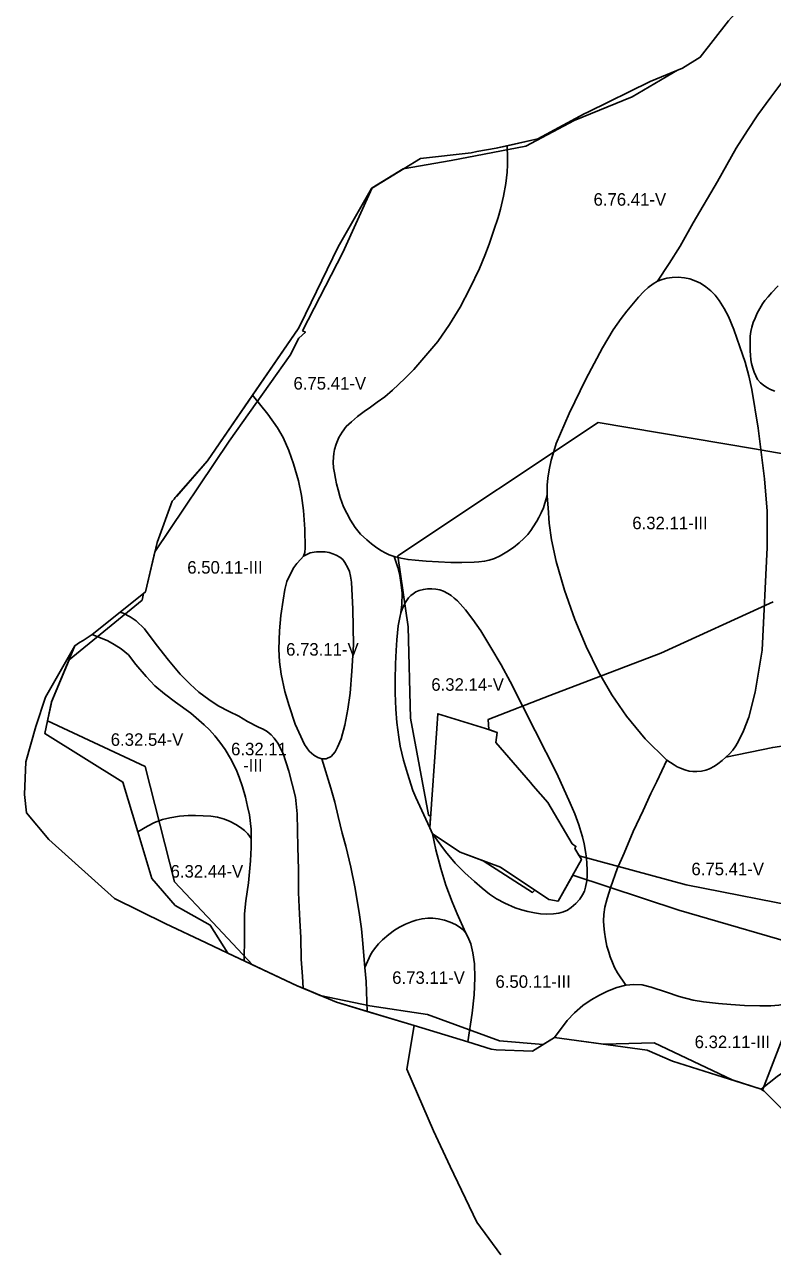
# Model space of a CAD drawing. Extents: x -555156 to -540209, y -1046851 to -1035695.
# Drawn here: x -545232 to -544635, y -1042568 to -1041591 of the extents above; entities that cross this region are included whole.
import ezdxf

# ---------------------------------------------------------------- set-up
doc = ezdxf.new("R2010")
doc.units = 0
for name, color, linetype in [('Vrstva 27', 7, 'Continuous'), ('Vrstva 28', 7, 'Continuous'), ('Vrstva 29', 7, 'Continuous')]:
    doc.layers.add(name, color=color, linetype=linetype)

msp = doc.modelspace()

# ---------------------------------------------------------------- linework, layer by layer
at = {"layer": 'Vrstva 28'}
for points in [[(-544846.66, -1041687.71), (-544822.15, -1041682.29), (-544785.01, -1041662.41), (-544782.28, -1041660.95), (-544732.45, -1041636.53), (-544706.67, -1041625.81), (-544692.4, -1041617.08), (-544669.81, -1041587.89), (-544667.51, -1041585.3), (-544652.1, -1041568.04), (-544642.56, -1041556.41), (-544641.15, -1041554.7), (-544627.44, -1041537.8), (-544618.31, -1041526.55), (-544597.99, -1041504.33), (-544579.99, -1041481.73), (-544578.85, -1041475.94), (-544576.99, -1041466.5), (-544570.58, -1041421.76), (-544570.32, -1041418.62), (-544569.32, -1041406.66), (-544568.61, -1041387.02), (-544567.8, -1041372.55)], [(-544669.81, -1041587.89), (-544692.4, -1041617.08), (-544706.67, -1041625.81), (-544732.45, -1041636.53), (-544782.28, -1041660.95), (-544785.01, -1041662.41), (-544811.22, -1041676.44), (-544822.15, -1041682.29), (-544855.46, -1041689.66), (-544870.74, -1041692.46), (-544875.3, -1041693.3), (-544915.78, -1041697.83), (-544954.95, -1041721.8), (-544981.68, -1041768.53), (-545011.97, -1041830.94), (-545013.49, -1041834.07), (-545085.98, -1041939.48), (-545110.52, -1041967.55), (-545110.82, -1041967.9), (-545111.62, -1041968.81), (-545112.68, -1041970.02), (-545114.1, -1041971.65), (-545126.15, -1042004.64), (-545135.45, -1042044.15), (-545177.97, -1042078.09), (-545185.22, -1042082.8), (-545188.03, -1042084.62), (-545191.76, -1042087.04), (-545215.32, -1042128.08), (-545222.89, -1042151.63), (-545231, -1042179.76), (-545232.1, -1042206), (-545230.38, -1042220.45), (-545212.6, -1042241.9), (-545160.15, -1042288.85), (-545119.62, -1042309.04), (-545087.05, -1042324.33), (-545069.69, -1042332.51), (-545014.29, -1042358.62), (-544982.93, -1042371.86), (-544920.79, -1042390.48), (-544926.73, -1042425.19), (-544905.36, -1042474.42), (-544892.12, -1042503.11), (-544870.74, -1042547.47), (-544851.56, -1042573.64)], [(-544626.51, -1041636.32), (-544636.08, -1041648.92), (-544646.38, -1041663.1), (-544654.61, -1041675.46), (-544663.75, -1041689.7), (-544678.59, -1041716.21), (-544698.08, -1041749.29), (-544708.47, -1041767.95), (-544717.16, -1041781.73), (-544726.5, -1041795.92)], [(-545049.88, -1041886.99), (-545013.49, -1041834.07), (-545011.97, -1041830.94), (-544981.68, -1041768.53), (-544954.95, -1041721.8), (-544915.78, -1041697.83), (-544875.3, -1041693.3), (-544870.74, -1041692.46), (-544855.46, -1041689.66), (-544846.66, -1041687.71)], [(-544846.66, -1041687.71), (-544846.27, -1041697.25)], [(-544846.27, -1041697.25), (-544846.27, -1041703.07), (-544846.63, -1041709), (-544847.6, -1041717.97), (-544849.66, -1041728.03), (-544851.96, -1041738.45), (-544853.9, -1041745.11), (-544857.17, -1041755.29), (-544861.04, -1041766.44), (-544864.55, -1041775.41), (-544868.62, -1041785.86), (-544876.46, -1041801.76), (-544884.09, -1041816.6), (-544892.78, -1041830.6), (-544902.11, -1041844.17), (-544911.64, -1041855.41), (-544921.18, -1041866.44), (-544928.39, -1041873.65), (-544938.13, -1041882.98), (-544944.31, -1041888.3), (-544950.37, -1041892.66), (-544955.7, -1041896.42), (-544960.9, -1041900.05), (-544966.11, -1041903.93), (-544970.95, -1041908.17), (-544975.19, -1041912.05), (-544978.46, -1041916.41), (-544981.01, -1041920.77), (-544983.07, -1041925.98), (-544984.4, -1041930.47), (-544984.91, -1041933.68), (-544985.25, -1041936.51), (-544985.46, -1041940.46), (-544985.25, -1041944.89), (-544984.63, -1041949.12), (-544983.73, -1041953.41), (-544982.83, -1041957.84), (-544981.66, -1041962.69), (-544980, -1041968.67), (-544977.33, -1041976.06), (-544974.67, -1041981.27), (-544971.76, -1041986.72), (-544968.01, -1041992.66), (-544963.65, -1041997.87), (-544958.8, -1042002.48), (-544954.93, -1042005.75), (-544950.57, -1042008.9), (-544946.88, -1042011.25), (-544943.98, -1042012.91), (-544940.79, -1042014.37), (-544936.78, -1042015.89)], [(-544814.62, -1041966.82), (-544814.62, -1041958.9), (-544814.26, -1041953.32), (-544813.05, -1041946.54), (-544811.47, -1041938.9), (-544809.41, -1041931.88), (-544807.48, -1041925.67), (-544797.1, -1041901.71), (-544783.89, -1041874.19), (-544770.57, -1041849.11), (-544761.97, -1041834.81), (-544755.7, -1041825.83), (-544751.14, -1041819.81), (-544745.81, -1041813.5), (-544741.66, -1041808.73), (-544737.5, -1041804.3), (-544734.04, -1041801.04), (-544729.96, -1041798.06), (-544726.5, -1041795.92)], [(-544726.5, -1041795.92), (-544722.83, -1041794.46), (-544719.1, -1041793.63), (-544714.74, -1041793.01), (-544710.03, -1041792.8), (-544705.12, -1041793.22)], [(-544705.12, -1041793.22), (-544700.76, -1041794.12), (-544695.91, -1041795.85), (-544692.31, -1041797.65), (-544687.95, -1041800.49), (-544683.94, -1041803.6), (-544680.55, -1041807.06), (-544677.24, -1041811.25), (-544673.25, -1041817.8), (-544669.98, -1041824.22), (-544665.62, -1041834.4), (-544660.77, -1041848.33), (-544656.53, -1041860.57), (-544653.51, -1041871.6), (-544651.22, -1041882.57), (-544646.14, -1041913.32), (-544641.05, -1041953.82), (-544638.93, -1041979.48), (-544638.93, -1042008.53), (-544642.98, -1042090.59), (-544648.67, -1042124.28), (-544653.64, -1042144.03), (-544657.76, -1042155.06), (-544661.87, -1042163.42), (-544663.91, -1042167.14), (-544666.47, -1042170.46), (-544669.03, -1042173.37), (-544671.87, -1042176.14)], [(-544632.93, -1041883.87), (-544636.39, -1041882.35), (-544639.3, -1041880.83), (-544641.86, -1041878.96), (-544644.35, -1041877.02), (-544646.64, -1041874.32), (-544648.09, -1041871.48), (-544649.33, -1041868.71), (-544650.37, -1041865.45), (-544651.41, -1041861.72), (-544652.07, -1041858.7), (-544652.41, -1041854.96), (-544652.55, -1041851.5), (-544652.69, -1041847.49), (-544652.69, -1041843.06), (-544652.62, -1041839.73), (-544652.07, -1041836.06), (-544651.24, -1041832.74), (-544650.13, -1041828.86), (-544648.61, -1041825.4), (-544646.88, -1041821.52), (-544644.73, -1041817.78), (-544642.73, -1041814.11), (-544640.72, -1041811.41), (-544638.23, -1041808.3), (-544635.55, -1041805.26), (-544630.23, -1041799.69)], [(-545155.58, -1042060.22), (-545135.45, -1042044.15), (-545126.15, -1042004.64), (-545114.1, -1041971.65), (-545112.68, -1041970.02), (-545111.62, -1041968.81), (-545110.82, -1041967.9), (-545085.98, -1041939.48), (-545049.88, -1041886.99)], [(-545049.88, -1041886.99), (-545037.74, -1041902.04)], [(-545037.74, -1041902.04), (-545030.11, -1041913.07), (-545025.45, -1041920.7), (-545021, -1041931.09), (-545017.18, -1041941.7), (-545013.37, -1041955.48), (-545010.82, -1041967.14), (-545009.34, -1041979.02), (-545008.28, -1041994.07), (-545007.86, -1042008.92), (-545008.28, -1042012.56), (-545009.25, -1042015.59)], [(-544936.78, -1042015.89), (-544931.66, -1042017.14), (-544925.78, -1042018.24), (-544920.17, -1042018.87), (-544911.31, -1042019.56), (-544901.56, -1042020.18), (-544891.52, -1042020.6), (-544882.94, -1042020.53), (-544873.04, -1042020.25), (-544869.34, -1042020.15), (-544864.7, -1042019.6), (-544860.97, -1042018.84), (-544856.75, -1042017.38), (-544852.32, -1042015.17), (-544846.78, -1042012.05), (-544841.66, -1042008.59), (-544837.09, -1042004.85), (-544833.22, -1042001.53), (-544830.1, -1041998.13), (-544827.69, -1041995.16), (-544825.75, -1041992.18), (-544822.98, -1041987.68), (-544821.25, -1041984.7), (-544819.45, -1041980.96), (-544817.65, -1041976.88), (-544816.41, -1041973.28), (-544815.37, -1041969.88), (-544814.62, -1041966.82)], [(-544814.62, -1041966.82), (-544814.62, -1041967.62)], [(-544814.62, -1041967.62), (-544813.89, -1041976.95), (-544813.05, -1041989.31), (-544811.23, -1042002.4), (-544807.6, -1042019.73), (-544800.72, -1042042.58), (-544792.45, -1042066.12), (-544783.55, -1042087.75), (-544773.8, -1042107.89), (-544763.06, -1042126.32), (-544751.4, -1042143.28), (-544736.35, -1042161.52), (-544718.99, -1042178.56)], [(-544994.68, -1042177.42), (-544997.71, -1042176.45), (-545001.1, -1042174.39), (-545004.73, -1042171.24), (-545008.43, -1042165.91), (-545015.84, -1042149.79), (-545020.72, -1042135.16), (-545024.11, -1042123.5), (-545027.08, -1042109.71), (-545028.56, -1042099.96), (-545028.98, -1042089.78), (-545028.39, -1042075.2), (-545027.3, -1042062.96), (-545025.48, -1042050.73), (-545024.15, -1042042.12), (-545022.57, -1042035.7), (-545019.42, -1042029.16), (-545016.88, -1042024.55), (-545014.58, -1042021.28), (-545011.31, -1042018.01), (-545009.25, -1042015.59)], [(-545009.25, -1042015.59), (-545008.28, -1042015.03), (-545007.18, -1042014.39), (-545005.59, -1042013.6), (-545004.01, -1042013.01), (-545002.39, -1042012.65), (-545000.77, -1042012.38), (-544998.83, -1042012.14), (-544995.66, -1042012.11), (-544992.06, -1042012.18)], [(-544992.06, -1042012.18), (-544988.88, -1042012.66), (-544985.76, -1042013.56), (-544983.06, -1042014.74), (-544980.29, -1042016.33), (-544977.94, -1042018.34), (-544976.14, -1042020.7), (-544973.79, -1042024.78), (-544972.41, -1042027.76), (-544971.64, -1042031.43), (-544970.88, -1042036.22), (-544969.91, -1042057.91), (-544969.37, -1042086.3), (-544970.7, -1042107.5), (-544972.03, -1042124.95), (-544973.73, -1042137.8), (-544976.15, -1042150.4), (-544979.18, -1042161.42), (-544982.09, -1042167.97), (-544983.9, -1042171.85), (-544987.29, -1042175.6), (-544991.17, -1042177.3), (-544994.68, -1042177.42)], [(-544931.47, -1042060.9), (-544930.63, -1042054.21), (-544930.39, -1042045.04), (-544931.24, -1042038.38), (-544932.33, -1042030.86), (-544933.9, -1042024.68), (-544936.78, -1042015.89)], [(-544931.47, -1042060.9), (-544930.5, -1042057.92), (-544929.48, -1042055.51), (-544928.29, -1042053.22), (-544927.06, -1042051.12), (-544925.36, -1042048.78), (-544923.58, -1042047.08), (-544921.72, -1042045.54), (-544919.51, -1042044.12), (-544916.78, -1042042.85), (-544913.54, -1042042.1), (-544910.34, -1042041.74), (-544906.78, -1042041.7), (-544903.49, -1042041.9)], [(-544903.49, -1042041.9), (-544900.37, -1042042.41), (-544897.44, -1042043.52), (-544894.12, -1042045.3), (-544891.28, -1042047.08), (-544888.82, -1042049.02), (-544886.3, -1042051.21), (-544880.01, -1042058.48), (-544873.95, -1042066.24), (-544867.53, -1042075.2), (-544859.54, -1042088.53), (-544851.42, -1042102.35), (-544844.12, -1042115.72), (-544824.2, -1042154.95), (-544807.03, -1042189.09), (-544796.32, -1042212.8), (-544792.52, -1042221.45), (-544789.26, -1042230.11), (-544787.67, -1042235.51), (-544786.43, -1042239.8), (-544785.25, -1042245.27), (-544784.14, -1042251.44), (-544783.38, -1042256.77), (-544782.95, -1042261.06), (-544782.74, -1042265.97), (-544782.81, -1042270.82), (-544783.02, -1042274.77), (-544784.06, -1042279.82), (-544784.96, -1042283.14), (-544786.41, -1042286.12), (-544788.7, -1042289.37), (-544791.67, -1042292.98), (-544795.41, -1042296.16), (-544798.39, -1042298.17), (-544801.64, -1042299.69), (-544805.24, -1042300.66), (-544809.73, -1042301.08), (-544814.92, -1042301.42), (-544819.98, -1042301.08), (-544824.89, -1042300.38), (-544830.01, -1042299.41), (-544835.27, -1042297.96), (-544840.15, -1042296.37), (-544848.38, -1042292.74), (-544855.04, -1042289.22), (-544860.61, -1042285.59), (-544866.67, -1042280.74), (-544872.72, -1042275.41), (-544880.35, -1042268.38), (-544888.1, -1042260.75), (-544895.98, -1042251.3), (-544906.15, -1042237.41)], [(-545177.97, -1042078.09), (-545155.58, -1042060.22)], [(-545155.58, -1042060.22), (-545153.2, -1042061.15)], [(-545153.2, -1042061.15), (-545147.63, -1042064.06), (-545142.78, -1042067.21), (-545136.12, -1042073.63), (-545126.92, -1042086.11), (-545116.99, -1042098.71), (-545107.66, -1042109.86), (-545099.67, -1042117.86), (-545092.89, -1042124.04), (-545084.9, -1042130.09), (-545077.39, -1042135.06), (-545068.55, -1042139.55), (-545061.04, -1042143.3), (-545053.89, -1042147.54), (-545045.29, -1042152.03), (-545041.56, -1042153.78), (-545038.31, -1042155.58), (-545034.99, -1042158.21), (-545032.57, -1042160.77), (-545029.66, -1042164.93), (-545025.58, -1042173.17), (-545020.87, -1042187.29), (-545015.61, -1042208), (-545014.34, -1042221.35), (-545013.7, -1042247.86), (-545013.28, -1042265.89), (-545013.26, -1042284.27), (-545012.84, -1042295.93), (-545012.2, -1042306.53), (-545011.36, -1042320.1), (-545011.14, -1042337.28), (-545010.08, -1042351.28), (-545009.47, -1042360.66)], [(-544908.49, -1042232.61), (-544916.48, -1042215.28), (-544919.66, -1042208.22), (-544922.02, -1042202.68), (-544926.26, -1042189.23), (-544929.28, -1042178.56), (-544931.95, -1042167.3), (-544933.16, -1042160.09), (-544934.86, -1042148.33), (-544935.58, -1042137.67), (-544936.19, -1042125.07), (-544936.19, -1042114.4), (-544935.82, -1042101.44), (-544935.34, -1042090.9), (-544934.73, -1042082.44), (-544933.62, -1042071.08), (-544932.37, -1042064.64), (-544931.47, -1042060.9)], [(-545191.76, -1042087.04), (-545188.03, -1042084.62), (-545185.22, -1042082.8), (-545177.97, -1042078.09)], [(-545177.97, -1042078.09), (-545165.55, -1042083.2)], [(-545191.76, -1042087.04), (-545210.41, -1042131.81)], [(-545165.55, -1042083.2), (-545160.35, -1042085.99), (-545154.9, -1042089.5), (-545149.08, -1042094.35), (-545143.15, -1042101.98), (-545135.03, -1042111.68), (-545127.89, -1042119.19), (-545120.38, -1042125.37), (-545111.42, -1042132.03), (-545099.31, -1042141), (-545088.53, -1042150.21), (-545084.44, -1042154.24), (-545080.2, -1042158.96), (-545076.09, -1042164.17), (-545071.73, -1042169.99), (-545067.61, -1042177.02), (-545063.13, -1042185.99), (-545060.58, -1042192.17), (-545057.92, -1042199.8), (-545055.5, -1042207.92), (-545053.92, -1042215.55), (-545052.47, -1042222.09), (-545051.18, -1042233.65), (-545051.06, -1042240.92)], [(-545210.41, -1042131.81), (-545215.82, -1042157.23), (-545153.48, -1042195.93), (-545141.58, -1042235.62)], [(-544908.49, -1042232.61), (-544902.88, -1042153.29), (-544902.03, -1042141.34), (-544863.97, -1042153.1)], [(-544863.97, -1042153.1), (-544854.48, -1042156.45), (-544855.75, -1042164.43), (-544828.03, -1042196.3), (-544825.75, -1042198.92), (-544814.16, -1042212.24), (-544794.83, -1042245.19), (-544791.77, -1042247.37), (-544792.6, -1042248.99), (-544787.38, -1042257.88), (-544805.97, -1042291.16), (-544813.37, -1042289.79), (-544851.94, -1042263.92), (-544884.06, -1042252.06), (-544906.15, -1042237.41)], [(-544671.87, -1042176.14), (-544634.47, -1042168.33), (-544625.75, -1042167.12), (-544617.15, -1042166.75), (-544607.7, -1042166.39), (-544600.8, -1042166.75)], [(-544718.99, -1042178.56), (-544713.25, -1042182.23), (-544710.83, -1042183.69), (-544708.2, -1042184.93), (-544704.74, -1042186.25), (-544701.28, -1042187.15), (-544698.3, -1042187.42), (-544695.19, -1042187.42), (-544691.38, -1042187.22), (-544687.99, -1042186.52), (-544684.95, -1042185.42), (-544680.93, -1042183.2), (-544678.3, -1042181.4), (-544674.98, -1042178.84), (-544671.87, -1042176.14)], [(-544994.68, -1042177.42), (-544987.41, -1042200.87), (-544984.26, -1042212.14), (-544981.6, -1042223.53), (-544978.33, -1042236.86), (-544975.42, -1042247.04), (-544971.34, -1042263.81), (-544968.16, -1042279.5), (-544964.77, -1042300.07), (-544963.08, -1042313.22), (-544961.81, -1042324.88), (-544960.96, -1042334.85), (-544960.32, -1042344.18)], [(-544751.85, -1042358.18), (-544758.43, -1042348.33), (-544760.86, -1042343.97), (-544762.45, -1042340.16), (-544764.39, -1042335.59), (-544765.56, -1042331.78), (-544766.95, -1042327.01), (-544767.98, -1042321.05), (-544768.88, -1042315.72), (-544769.51, -1042310.73), (-544769.78, -1042306.79), (-544769.53, -1042301.61), (-544768.56, -1042295.8), (-544766.87, -1042288.89), (-544763.84, -1042279.68), (-544758.76, -1042265.38), (-544753.31, -1042252.78), (-544745.92, -1042235.33), (-544738.05, -1042218.73), (-544731.95, -1042205.22), (-544727.23, -1042195.53), (-544718.99, -1042178.56)], [(-545141.58, -1042235.62), (-545133.95, -1042231.09), (-545128.34, -1042228.32), (-545121.91, -1042225.97), (-545115.89, -1042224.39), (-545108.2, -1042223.22), (-545101.35, -1042222.66), (-545095.54, -1042222.66), (-545089.31, -1042222.8)], [(-545089.31, -1042222.8), (-545083.29, -1042223.22), (-545077.82, -1042224.12), (-545072.36, -1042225.71), (-545067.79, -1042227.51), (-545063.36, -1042229.79), (-545059.55, -1042232.22), (-545056.3, -1042234.71), (-545053.67, -1042237.41), (-545051.06, -1042240.92)], [(-545069.69, -1042332.51), (-545083.71, -1042310.17), (-545111.79, -1042294.51), (-545130.42, -1042272.86), (-545141.58, -1042235.62)], [(-544906.15, -1042237.41), (-544908.49, -1042232.61)], [(-545051.06, -1042240.92), (-545051.06, -1042248.19), (-545051.55, -1042258.73), (-545053.24, -1042276.3), (-545055.44, -1042290.84), (-545056.28, -1042301.23), (-545056.5, -1042309.5), (-545056.5, -1042319.68), (-545056.76, -1042338.61)], [(-544879.94, -1042316.05), (-544886.54, -1042301.29), (-544890.54, -1042291.72), (-544895.63, -1042278.39), (-544899.62, -1042264.94), (-544903.5, -1042250.15), (-544906.15, -1042237.41)], [(-544960.32, -1042344.18), (-544955.7, -1042334.01), (-544954.11, -1042331.17), (-544951.62, -1042327.71), (-544949.4, -1042325.08), (-544946.15, -1042321.97), (-544941.24, -1042317.67), (-544936.53, -1042314.28), (-544932.66, -1042311.93), (-544927.88, -1042309.5), (-544922.55, -1042307.36), (-544919.23, -1042306.25), (-544914.59, -1042305.14), (-544909.89, -1042304.65), (-544905.94, -1042304.59), (-544901.72, -1042305.07)], [(-544901.72, -1042305.07), (-544896.6, -1042306.18), (-544892.03, -1042307.84), (-544887.81, -1042309.78), (-544885.04, -1042311.44), (-544881.72, -1042313.93), (-544879.94, -1042316.05)], [(-544879.94, -1042316.05), (-544878, -1042319.58), (-544875.65, -1042325.05), (-544873.99, -1042332.25), (-544872.74, -1042341.14), (-544872.5, -1042352.17), (-544872.86, -1042365.99), (-544874.56, -1042380.4), (-544878.09, -1042403.5)], [(-544751.85, -1042358.18), (-544745.43, -1042357.58), (-544738.89, -1042357.82), (-544731.5, -1042359.63), (-544719.51, -1042363.88), (-544709.34, -1042367.15), (-544698.2, -1042370.18), (-544689.84, -1042371.51), (-544677.85, -1042372.84), (-544667.92, -1042373.69), (-544657.14, -1042374.42), (-544644.79, -1042374.66), (-544636.07, -1042374.54), (-544629.54, -1042374.04), (-544624.09, -1042373.19), (-544618.76, -1042371.98), (-544614.04, -1042370.16), (-544607.01, -1042366.16), (-544600.23, -1042360.95), (-544594.3, -1042355.14), (-544584.97, -1042345.68), (-544560.69, -1042316.32)], [(-545056.76, -1042338.61), (-545069.69, -1042332.51)], [(-545009.47, -1042360.66), (-545014.29, -1042358.62), (-545056.76, -1042338.61)], [(-544958.33, -1042379.23), (-544959.26, -1042355.2), (-544960.32, -1042344.18)], [(-544958.33, -1042379.23), (-544982.93, -1042371.86), (-545009.47, -1042360.66)], [(-544808.84, -1042400.07), (-544798.6, -1042386.41), (-544792.9, -1042380.23), (-544786.12, -1042374.3), (-544779.58, -1042369.81), (-544772.8, -1042366.06), (-544766.38, -1042363.03), (-544758.99, -1042360), (-544751.85, -1042358.18)], [(-544920.79, -1042390.48), (-544958.33, -1042379.23)], [(-544878.09, -1042403.5), (-544920.79, -1042390.48)], [(-544808.84, -1042400.07), (-544826.35, -1042410.79), (-544855.28, -1042409.75), (-544859.45, -1042409.19), (-544878.09, -1042403.5)], [(-544643.83, -1042441.2), (-544714.71, -1042418.75), (-544734.85, -1042410.05), (-544808.84, -1042400.07)], [(-544643.83, -1042441.2), (-544631.13, -1042431.14), (-544625.2, -1042427.02), (-544615.87, -1042421.08), (-544605.46, -1042415.03), (-544594.08, -1042408), (-544584.15, -1042402.39)], [(-544580.26, -1042483.76), (-544616.64, -1042467.62), (-544641.4, -1042442.86), (-544643.83, -1042441.2)]]:
    msp.add_lwpolyline(points, dxfattribs=at)
at = {"layer": 'Vrstva 29'}
for points in [[(-544669.81, -1041587.89), (-544692.4, -1041617.08), (-544706.67, -1041625.81), (-544710.465936, -1041627.38845), (-544746.815979, -1041648.804993), (-544793.029907, -1041667.580017), (-544831.747009, -1041688.09198), (-544891.302002, -1041699.471985), (-544929.636627, -1041706.309534), (-544954.302974, -1041721.404054), (-544977.955017, -1041773.01001), (-545010.067055, -1041835.629142)], [(-545010.067055, -1041835.629142), (-545007.76, -1041836.68), (-545013.078762, -1041841.502032), (-545019.950989, -1041854.903015), (-545068.61499, -1041923.666016), (-545127.885759, -1042012.014178), (-545135.45, -1042044.15), (-545136.974728, -1042045.367057), (-545138.125977, -1042050.598022), (-545196.431921, -1042098.255115), (-545210.207635, -1042131.324216), (-545211.118049, -1042135.136914), (-545213.637703, -1042146.976028), (-545135.702026, -1042183.651001), (-545112.268005, -1042275.632019), (-545081.651001, -1042308.13501), (-545049.941394, -1042341.822628), (-545014.29, -1042358.62), (-545009.47, -1042360.66), (-544995.889316, -1042366.39111), (-544956.218994, -1042374.700012), (-544910.151978, -1042381.658997), (-544852.65802, -1042402.713989), (-544817.923601, -1042405.631176), (-544808.84, -1042400.07), (-544769.674127, -1042405.352814), (-544729.22699, -1042404.333984), (-544666.929834, -1042433.883532), (-544643.83, -1042441.2), (-544642.609494, -1042442.033761), (-544599.630981, -1042330.317017), (-544709.434998, -1042298.135986), (-544794.254497, -1042270.186792), (-544805.97, -1042291.16), (-544813.37, -1042289.79), (-544824.39929, -1042282.39234), (-544826.328003, -1042284.140991), (-544865.886631, -1042258.766741), (-544871.48, -1042256.7), (-544884.06, -1042252.06), (-544906.15, -1042237.41), (-544908.49, -1042232.61), (-544907.84958, -1042223.555074), (-544909.549988, -1042222.127014), (-544923.929993, -1042145.034973), (-544925.669006, -1042071.95697), (-544933.822998, -1042015.344971), (-544774.06897, -1041908.779907), (-544649.171997, -1041929.914001), (-544473.088013, -1041960.538025)], [(-544634.208984, -1042051.930969), (-544723.911011, -1042093.055908), (-544812.664001, -1042126.879028), (-544861.708008, -1042145.893005), (-544861.295787, -1042154.044006), (-544854.48, -1042156.45), (-544855.75, -1042164.43), (-544828.03, -1042196.3), (-544825.75, -1042198.92), (-544814.16, -1042212.24), (-544794.83, -1042245.19), (-544791.77, -1042247.37), (-544792.6, -1042248.99), (-544789.154726, -1042254.857526), (-544703.695007, -1042278.034973), (-544603.439026, -1042297.830994)]]:
    msp.add_lwpolyline(points, dxfattribs=at)

# ---------------------------------------------------------------- texts
at = {"layer": 'Vrstva 27'}
for s, p in [('6.76.41-V', (-544777.651006, -1041735.64)), ('6.75.41-V', (-545017.271006, -1041882.49)), ('6.32.11-III', (-544746.696548, -1041994.02)), ('6.50.11-III', (-545102.086548, -1042029.48)), ('6.73.11-V', (-545023.171006, -1042094.98)), ('6.32.14-V', (-544907.200288, -1042123.05)), ('6.32.54-V', (-545163.210884, -1042167.01)), ('6.32.11', (-545067.087261, -1042174.58)), ('-III', (-545057.482769, -1042187.58)), ('6.32.44-V', (-545115.420884, -1042272.24)), ('6.75.41-V', (-544699.480288, -1042270.36)), ('6.73.11-V', (-544938.411006, -1042357.1)), ('6.50.11-III', (-544855.976548, -1042360.28)), ('6.32.11-III', (-544696.906548, -1042408.45))]:
    msp.add_text(s, height=10, dxfattribs=at).set_placement(p)

doc.saveas('drawing.dxf')
